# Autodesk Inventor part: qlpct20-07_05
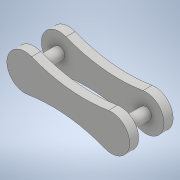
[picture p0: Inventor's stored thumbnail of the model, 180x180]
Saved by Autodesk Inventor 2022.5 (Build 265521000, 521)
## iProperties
Part Number: qlpct20-07_05
Material: 一般
Document SubType Name: Modeling
Designer: ImaoCorp
Density: 1 g/cm^3
Appearance: 既定
Author: ImaoCorp
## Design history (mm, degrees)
feature "qlpct20-07_05"
node "ソリッド1"
